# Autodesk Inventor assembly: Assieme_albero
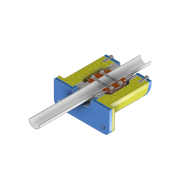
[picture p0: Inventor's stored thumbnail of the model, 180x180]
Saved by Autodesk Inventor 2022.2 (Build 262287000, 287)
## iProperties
Created: 2025-03
Part Number: Assieme_albero
Document SubType Name: Assembly
Designer: 18907419
Author: 18907419
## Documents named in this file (11)
- C:\Users\18907419\Desktop\albero\Assieme_albero.iam
- C:\Users\18907419\Desktop\albero\albero_20mm.ipt
- C:\Users\18907419\Documents\Inventor\Content Center Files\R2022\it-IT\STN 024720 SKF (B)\STN 024720 SKF (B) - SKF 32004 X.ipt
- C:\Users\18907419\Desktop\albero\blocca_albero.ipt
- C:\Users\18907419\Desktop\albero\spallamento_01.ipt
- C:\Users\18907419\Desktop\albero\base_blocco_albero.ipt
- C:\Users\18907419\Desktop\albero\blocco_cuscinetto_superiore.ipt
- C:\Users\18907419\Documents\Inventor\Content Center Files\R2022\it-IT\ANSI B18.3.1M(6)\ANSI B18.3.1M - M3x0,5 x 35(1).ipt
- C:\Users\18907419\Documents\Inventor\Content Center Files\R2022\it-IT\AS 1112 (2)\AS 1112 - M3  Tipo 5.ipt
- C:\Users\18907419\Desktop\albero\dado_fusione.ipt
- C:\Users\18907419\Documents\Inventor\Content Center Files\R2022\it-IT\AS 1427(05)\AS 1427 - M3 x 12(5) II.ipt
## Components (20 placed, 10 different names)
1. albero_20mm:1
2. blocca_albero:1 — Allineato:1, Allineato:3, Allineato:4
3. STN 024720 SKF- Cuscinetto a rulli rastremati SKF 32004 X:2
4. STN 024720 SKF- Cuscinetto a rulli rastremati SKF 32004 X:3 — Allineato:5
5. spallamento_01:1 — Allineato:2, Rotazionale:1, Rotazionale:2, Coincidente:2
6. base_blocco_albero:1 — Allineato:3
7. blocco_cuscinetto_superiore:1 — Allineato:4, Allineato:5, Rotazionale:3
8. Vite forgiata a testa incassata - Metrico M3x0,5 x 35:1 — Rotazionale:1
9. Vite forgiata a testa incassata - Metrico M3x0,5 x 35:2 — Rotazionale:2
10. AS 1112 (2) - Metrico M3  Tipo 5:1 — Coincidente:2
11. AS 1112 (2) - Metrico M3  Tipo 5:2
12. AS 1112 (2) - Metrico M3  Tipo 5:3
13. AS 1427 H - Metrico M3 x 12:1
14. AS 1427 H - Metrico M3 x 12:2
15. AS 1427 H - Metrico M3 x 12:3
16. AS 1427 H - Metrico M3 x 12:4
17. dado_fusione:1 — Rotazionale:3
18. dado_fusione:2
19. dado_fusione:3
20. dado_fusione:4
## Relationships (9: Flush 5, RevoluteJoint 3, Mate 1)
- Allineato:1 [Flush]: blocca_albero:1
- Allineato:2 [Flush]: spallamento_01:1
- Allineato:3 [Flush]: blocca_albero:1 ↔ base_blocco_albero:1
- Allineato:4 [Flush]: blocca_albero:1 ↔ blocco_cuscinetto_superiore:1
- Allineato:5 [Flush]: STN 024720 SKF- Cuscinetto a rulli rastremati SKF 32004 X:3 ↔ blocco_cuscinetto_superiore:1
- Rotazionale:1 [RevoluteJoint]: spallamento_01:1 ↔ Vite forgiata a testa incassata - Metrico M3x0,5 x 35:1
- Rotazionale:2 [RevoluteJoint]: spallamento_01:1 ↔ Vite forgiata a testa incassata - Metrico M3x0,5 x 35:2
- Coincidente:2 [Mate]: spallamento_01:1 ↔ AS 1112 (2) - Metrico M3  Tipo 5:1
- Rotazionale:3 [RevoluteJoint]: blocco_cuscinetto_superiore:1 ↔ dado_fusione:1
